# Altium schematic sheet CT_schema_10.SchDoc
size 281 x 153 mm
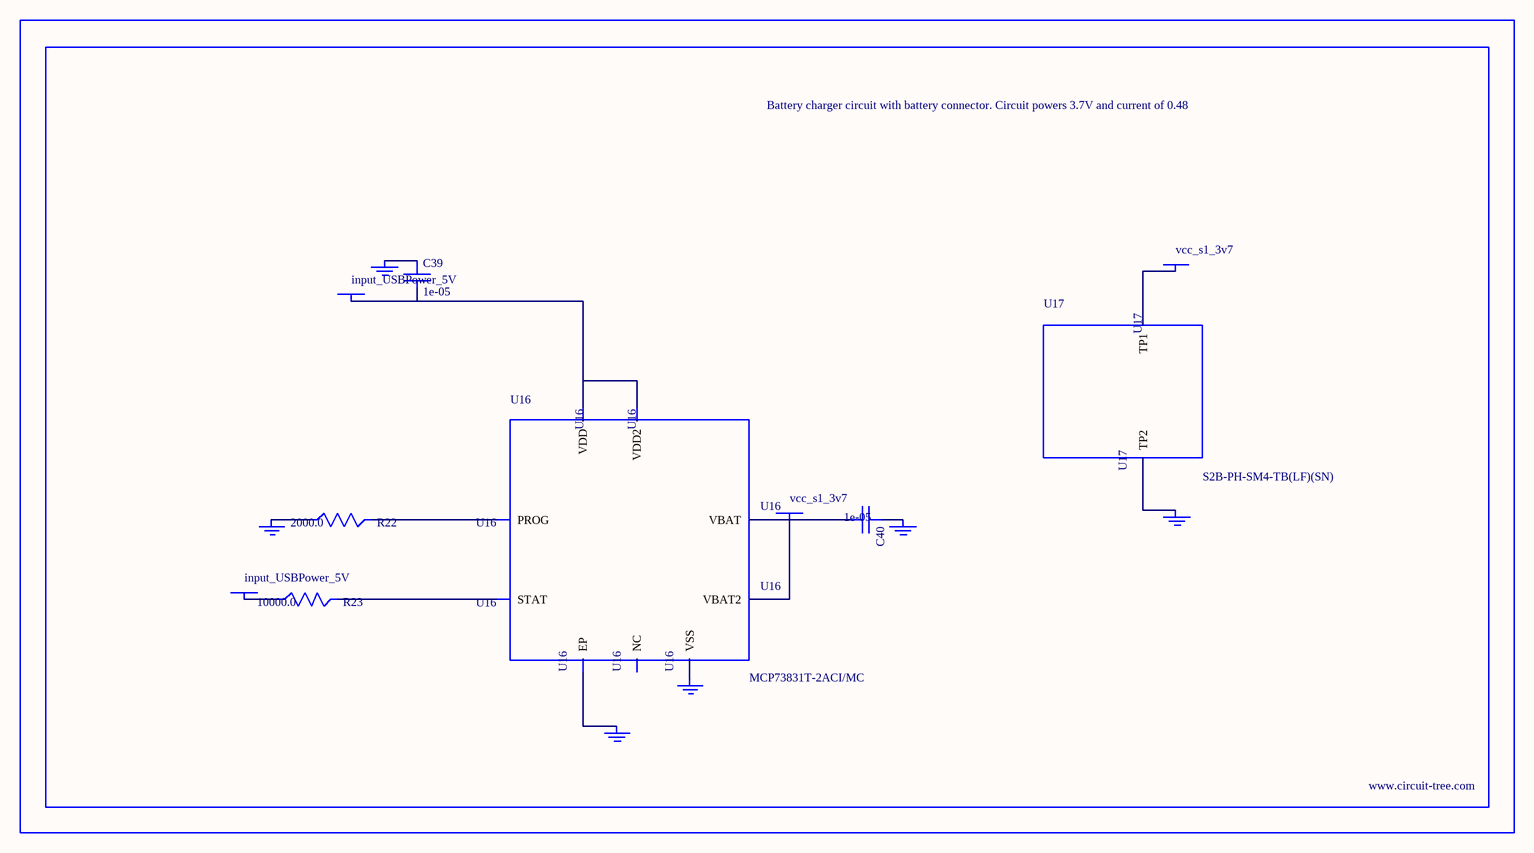
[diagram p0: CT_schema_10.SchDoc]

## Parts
BORDER9  (no value)
C39  1e-05  [C1206]
C40  1e-05  [C1206]
GND_INSTANCE_9_0  (no value)
GND_INSTANCE_9_1  (no value)
GND_INSTANCE_9_2  (no value)
GND_INSTANCE_9_3  (no value)
GND_INSTANCE_9_4  (no value)
GND_INSTANCE_9_5  (no value)
POWER_INSTANCE_9_0  input_USBPower_5V
POWER_INSTANCE_9_1  input_USBPower_5V
POWER_INSTANCE_9_2  vcc_s1_3v7
POWER_INSTANCE_9_3  vcc_s1_3v7
R22  2000.0  [R0603]
R23  10000.0  [R0603]
U16  MCP73831T-2ACI/MC  [DFN8_2X3MC]
U17  S2B-PH-SM4-TB(LF)(SN)  [JST-2-SMD]

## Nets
NetC39_1: C39.1 GND_INSTANCE_9_0.0(GND)
NetC39_2: C39.2 POWER_INSTANCE_9_0.0(PWR) U16.1(VDD) U16.2(VDD2)
NetC40_1: C40.1 GND_INSTANCE_9_1.0(GND)
NetC40_2: C40.2 POWER_INSTANCE_9_2.0(PWR) U16.3(VBAT) U16.4(VBAT2)
NetGND_INSTANCE_9_2_0: GND_INSTANCE_9_2.0(GND) R22.1
NetGND_INSTANCE_9_3_0: GND_INSTANCE_9_3.0(GND) U16.9(EP)
NetGND_INSTANCE_9_4_0: GND_INSTANCE_9_4.0(GND) U16.6(VSS)
NetGND_INSTANCE_9_5_0: GND_INSTANCE_9_5.0(GND) U17.2(TP2)
NetPOWER_INSTANCE_9_1_0: POWER_INSTANCE_9_1.0(PWR) R23.1
NetPOWER_INSTANCE_9_3_0: POWER_INSTANCE_9_3.0(PWR) U17.1(TP1)
NetR22_2: R22.2 U16.8(PROG)
NetR23_2: R23.2 U16.5(STAT)

Not connected (* = marked no-connect by the designer): U16 7(NC)

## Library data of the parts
BORDER9 = BORDER_PAGE9
C39 C40 = C1206C106K3RACTU
GND_INSTANCE_9_0-GND_INSTANCE_9_5 = GND
POWER_INSTANCE_9_0-POWER_INSTANCE_9_3 = PWR
R22 = RC0603JR-072KL
R23 = RC0603JR-0710KL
